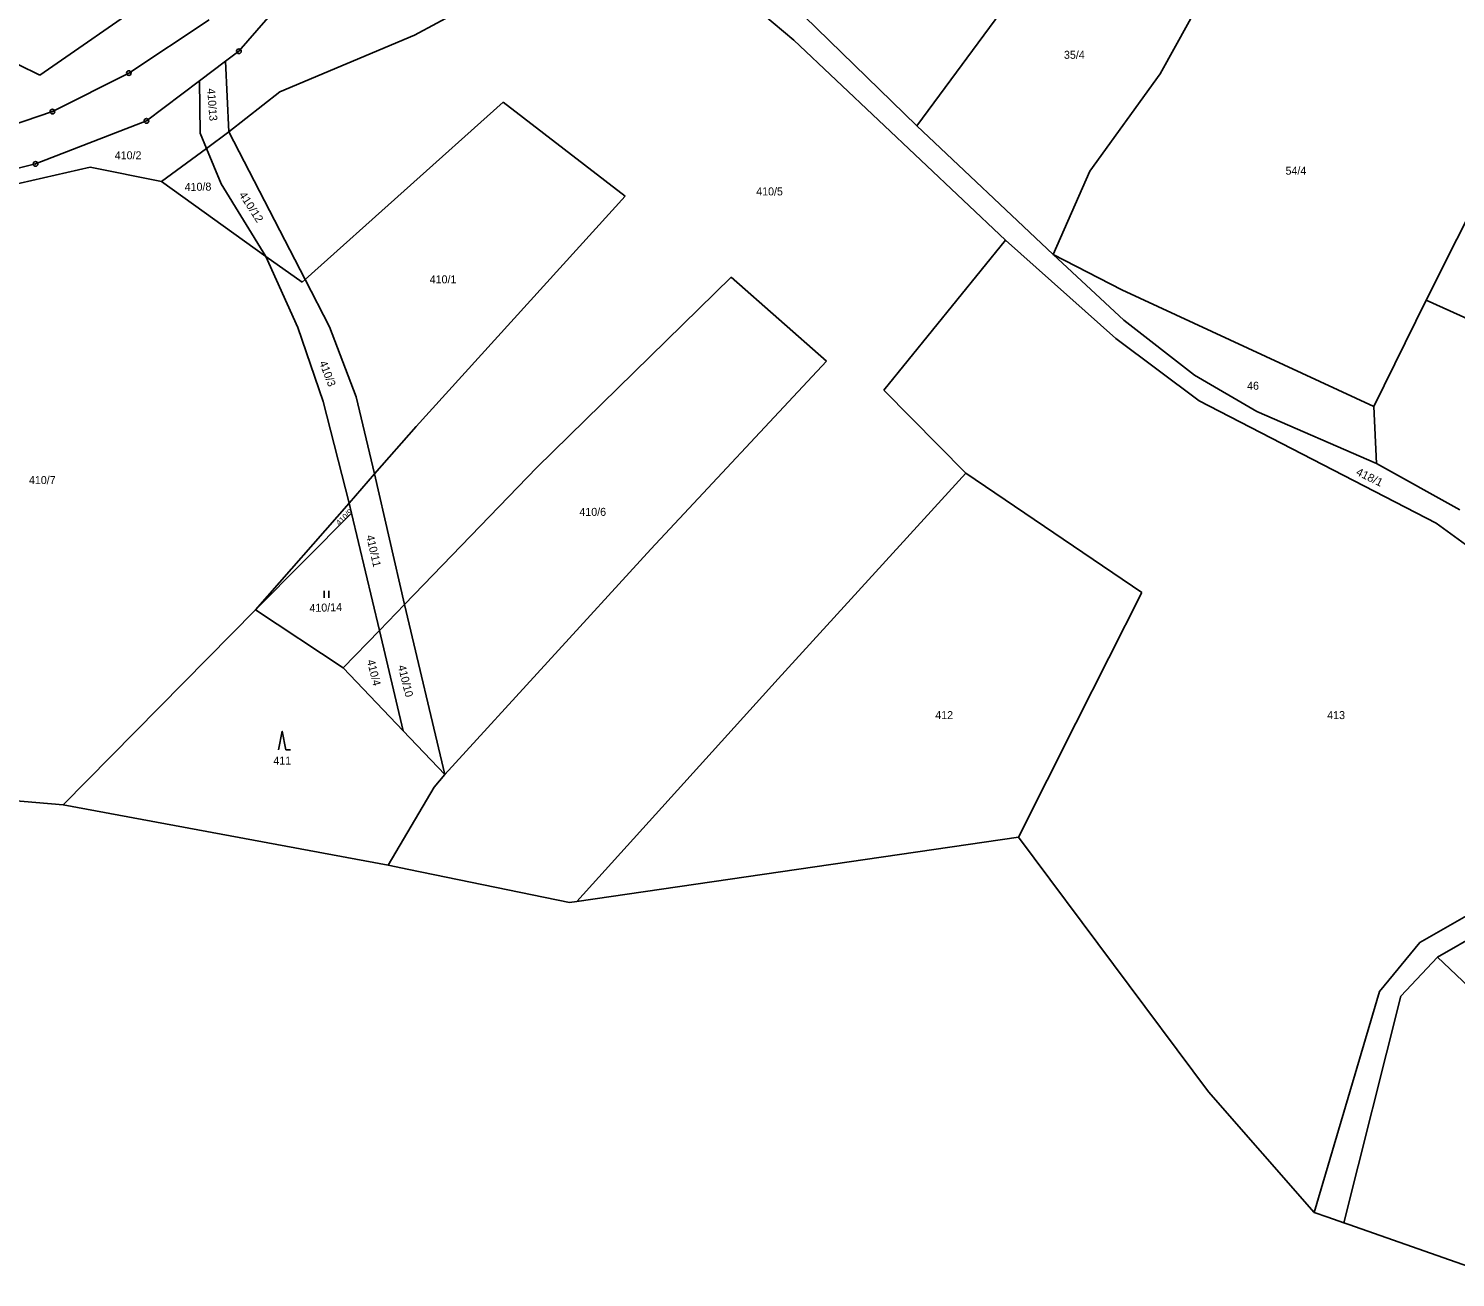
# Model space of a CAD drawing. Extents: x -791548 to -789311, y -1142631 to -1140855.
# Drawn here: x -790444.3 to -790140.3, y -1142554.4 to -1142288.4 of the extents above; entities that cross this region are included whole.
import ezdxf
from ezdxf.enums import TextEntityAlignment as Align

# ---------------------------------------------------------------- set-up
doc = ezdxf.new("R2010")
doc.units = 0
doc.header["$LTSCALE"] = 0.68
for name, color, linetype, lineweight in [('1', 7, 'Continuous', 25), ('3', 7, 'Continuous', 25), ('8', 7, 'Continuous', 25)]:
    doc.layers.add(name, color=color, linetype=linetype, lineweight=lineweight)
doc.layers.add('2', color=7, linetype='Continuous')

msp = doc.modelspace()

# ---------------------------------------------------------------- linework, layer by layer
at = {"layer": '1'}
for p, q in [((-790223.12, -1142265.83), (-790255.11, -1142309.11)), ((-790203.27, -1142298.05), (-790185.55, -1142266.07)), ((-790296.49, -1142278.02), (-790281.3, -1142290.85)), ((-790441.89, -1142298.31), (-790418.1, -1142281.74)), ((-790399.5, -1142293.19), (-790388.19, -1142280.16)), ((-790347.8, -1142282.01), (-790362.11, -1142289.76)), ((-790255.11, -1142309.11), (-790279.1, -1142285.75)), ((-790422.96, -1142297.87), (-790405.82, -1142286.48)), ((-790362.11, -1142289.76), (-790390.8, -1142301.83)), ((-790281.3, -1142290.85), (-790236.2, -1142333.47)), ((-790402.36, -1142295.33), (-790399.5, -1142293.19)), ((-790446.56, -1142296.04), (-790441.89, -1142298.31)), ((-790439.25, -1142306.06), (-790422.96, -1142297.87)), ((-790407.91, -1142299.51), (-790402.36, -1142295.33)), ((-790401.69, -1142310.37), (-790402.36, -1142295.33)), ((-790218.22, -1142318.77), (-790203.27, -1142298.05)), ((-790419.22, -1142308.03), (-790407.91, -1142299.51)), ((-790407.91, -1142299.51), (-790407.78, -1142310.66)), ((-790390.8, -1142301.83), (-790401.69, -1142310.37)), ((-790343.23, -1142304.06), (-790385.37, -1142341.83)), ((-790317.19, -1142324.04), (-790343.23, -1142304.06)), ((-790456.3, -1142311.85), (-790439.25, -1142306.06)), ((-790442.82, -1142317.2), (-790419.22, -1142308.03)), ((-790226.04, -1142336.49), (-790255.11, -1142309.11)), ((-790407.78, -1142310.66), (-790406.42, -1142313.95)), ((-790406.42, -1142313.95), (-790401.69, -1142310.37)), ((-790385.37, -1142341.83), (-790401.69, -1142310.37)), ((-790416.01, -1142320.96), (-790406.42, -1142313.95)), ((-790406.42, -1142313.95), (-790403.31, -1142321.44)), ((-790457.99, -1142320.89), (-790442.82, -1142317.2)), ((-790431.21, -1142317.88), (-790455.86, -1142323.56)), ((-790416.01, -1142320.96), (-790431.21, -1142317.88)), ((-790226.04, -1142336.49), (-790218.22, -1142318.77)), ((-790393.78, -1142336.93), (-790416.01, -1142320.96)), ((-790403.31, -1142321.44), (-790393.78, -1142336.93)), ((-790146.61, -1142346.2), (-790133.54, -1142320.2)), ((-790361.77, -1142373.14), (-790317.19, -1142324.04)), ((-790236.2, -1142333.47), (-790262.09, -1142365.36)), ((-790236.2, -1142333.47), (-790212.71, -1142354.38)), ((-790386.04, -1142342.4), (-790393.78, -1142336.93)), ((-790393.78, -1142336.93), (-790386.94, -1142352.06)), ((-790226.04, -1142336.49), (-790211.41, -1142344.05)), ((-790211.01, -1142350.49), (-790226.04, -1142336.49)), ((-790385.37, -1142341.83), (-790386.04, -1142342.4)), ((-790380.18, -1142351.87), (-790385.37, -1142341.83)), ((-790294.63, -1142341.3), (-790336.01, -1142381.89)), ((-790274.31, -1142359.25), (-790294.63, -1142341.3)), ((-790211.41, -1142344.05), (-790157.74, -1142368.84)), ((-790146.61, -1142346.2), (-790157.74, -1142368.84)), ((-790080.46, -1142376.06), (-790146.61, -1142346.2)), ((-790386.94, -1142352.06), (-790381.54, -1142367.82)), ((-790374.56, -1142366.81), (-790380.18, -1142351.87)), ((-790195.93, -1142362.21), (-790211.01, -1142350.49)), ((-790212.71, -1142354.38), (-790194.97, -1142367.69)), ((-790311.78, -1142399.26), (-790274.31, -1142359.25)), ((-790182.66, -1142369.94), (-790195.93, -1142362.21)), ((-790381.54, -1142367.82), (-790376.04, -1142389.44)), ((-790370.6, -1142383.22), (-790374.56, -1142366.81)), ((-790262.09, -1142365.36), (-790244.65, -1142383.04)), ((-790194.97, -1142367.69), (-790144.43, -1142393.74)), ((-790157.14, -1142381.01), (-790182.66, -1142369.94)), ((-790157.74, -1142368.84), (-790157.14, -1142381.01)), ((-790370.6, -1142383.22), (-790361.77, -1142373.14)), ((-790376.04, -1142389.44), (-790370.6, -1142383.22)), ((-790364.25, -1142411.05), (-790370.6, -1142383.22)), ((-790336.01, -1142381.89), (-790364.25, -1142411.05)), ((-790284.64, -1142426.91), (-790244.65, -1142383.04)), ((-790244.65, -1142383.04), (-790207.13, -1142408.5)), ((-790139.43, -1142390.88), (-790157.14, -1142381.01)), ((-790395.95, -1142412.18), (-790376.04, -1142389.44)), ((-790375.51, -1142391.6), (-790395.95, -1142412.18)), ((-790376.04, -1142389.44), (-790375.51, -1142391.6)), ((-790375.51, -1142391.6), (-790369.59, -1142416.55)), ((-790144.43, -1142393.74), (-790105.81, -1142421.92)), ((-790355.64, -1142447.23), (-790311.78, -1142399.26)), ((-790207.13, -1142408.5), (-790221.19, -1142436.3)), ((-790395.95, -1142412.18), (-790436.94, -1142453.75)), ((-790395.95, -1142412.18), (-790377.3, -1142424.52)), ((-790364.25, -1142411.05), (-790369.59, -1142416.55)), ((-790355.64, -1142447.23), (-790364.25, -1142411.05)), ((-790369.59, -1142416.55), (-790377.3, -1142424.52)), ((-790369.59, -1142416.55), (-790364.51, -1142437.93)), ((-790377.3, -1142424.52), (-790364.51, -1142437.93)), ((-790327.51, -1142474.31), (-790284.64, -1142426.91)), ((-790364.51, -1142437.93), (-790355.64, -1142447.23)), ((-790221.19, -1142436.3), (-790233.4, -1142460.6)), ((-790436.94, -1142453.75), (-790478.69, -1142450.06)), ((-790357.92, -1142449.92), (-790367.73, -1142466.58)), ((-790355.64, -1142447.23), (-790357.92, -1142449.92)), ((-790367.73, -1142466.58), (-790436.94, -1142453.75)), ((-790233.4, -1142460.6), (-790327.51, -1142474.31)), ((-790192.98, -1142514.81), (-790233.4, -1142460.6)), ((-790112.31, -1142462.65), (-790147.93, -1142483.02)), ((-790363.28, -1142467.49), (-790367.73, -1142466.58)), ((-790329.06, -1142474.53), (-790363.28, -1142467.49)), ((-790327.51, -1142474.31), (-790329.06, -1142474.53)), ((-790147.93, -1142483.02), (-790156.49, -1142493.47)), ((-790144.19, -1142486.18), (-790134.99, -1142480.92)), ((-790151.97, -1142494.46), (-790144.19, -1142486.18)), ((-790144.19, -1142486.18), (-790114.15, -1142514.52)), ((-790156.49, -1142493.47), (-790170.41, -1142540.54)), ((-790164.12, -1142542.75), (-790151.97, -1142494.46)), ((-790170.41, -1142540.54), (-790192.98, -1142514.81)), ((-790167.53, -1142541.56), (-790170.41, -1142540.54)), ((-790164.12, -1142542.75), (-790167.53, -1142541.56)), ((-790163.09, -1142543.11), (-790164.12, -1142542.75)), ((-790130.99, -1142554.38), (-790163.09, -1142543.11))]:
    msp.add_line(p, q, dxfattribs=at)
at = {"layer": '3'}
for p, q in [((-790381.321, -1142409.6), (-790381.321, -1142408.1)), ((-790380.32, -1142409.6), (-790380.32, -1142408.1)), ((-790389.54, -1142442.03), (-790388.544, -1142442.03))]:
    msp.add_line(p, q, dxfattribs=at)
msp.add_lwpolyline([(-790389.54, -1142442.03), (-790390.29, -1142438.03), (-790391.04, -1142442.03)], dxfattribs=at)
at = {"layer": '8'}
for centre, radius in [((-790399.4999, -1142293.19), 0.5), ((-790399.4999, -1142293.19), 0.0303), ((-790422.9599, -1142297.87), 0.5), ((-790422.9599, -1142297.87), 0.0303), ((-790439.2499, -1142306.06), 0.5), ((-790439.2499, -1142306.06), 0.0303), ((-790419.2199, -1142308.03), 0.5), ((-790419.2199, -1142308.03), 0.0303), ((-790442.8199, -1142317.2), 0.5), ((-790442.8199, -1142317.2), 0.0303)]:
    msp.add_circle(centre, radius, dxfattribs=at)

# ---------------------------------------------------------------- texts
at = {"layer": '2'}
for s, p in [('35/4', (-790221.529, -1142294.812)), ('410/2', (-790423.11, -1142316.222)), ('54/4', (-790174.329, -1142319.502)), ('410/5', (-790286.46, -1142323.912)), ('410/1', (-790356.02, -1142342.642)), ('46', (-790183.469, -1142365.302)), ('410/7', (-790441.4, -1142385.392)), ('410/6', (-790324.13, -1142392.162)), ('412', (-790249.269, -1142435.452)), ('413', (-790165.769, -1142435.452)), ('411', (-790390.289, -1142445.162))]:
    msp.add_text(s, height=1.7, dxfattribs=at).set_placement(p, align=Align.CENTER)
for s, rotation, p in [('410/13', 274, (-790406.0211, -1142304.6392)), ('410/8', 1, (-790408.2098, -1142322.9224)), ('410/3', 291, (-790381.4073, -1142362.1634)), ('410/11', 283, (-790371.6268, -1142399.8248)), ('410/14', 2, (-790380.9797, -1142412.5405)), ('410/4', 284, (-790371.5678, -1142425.7644)), ('410/10', 284, (-790364.8182, -1142427.5344))]:
    msp.add_text(s, height=1.7, rotation=rotation, dxfattribs=at).set_placement(p, align=Align.CENTER)
for s, height, rotation, width, p in [('410/12', 1.7, 303, 1.05, (-790397.5919, -1142326.8241)), ('418/1', 1.7, 334, 1.05, (-790159.0026, -1142384.6746)), ('410/9', 1.14, 44, 1.1, (-790376.6705, -1142392.8403))]:
    msp.add_text(s, height=height, rotation=rotation, dxfattribs=dict(at, width=width)).set_placement(p, align=Align.CENTER)

doc.saveas('drawing.dxf')
